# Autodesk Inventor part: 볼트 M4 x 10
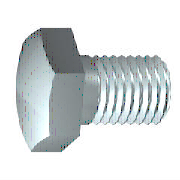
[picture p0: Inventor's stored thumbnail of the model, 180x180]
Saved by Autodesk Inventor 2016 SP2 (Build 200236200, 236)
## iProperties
Created: 2012-02
Part Number: 볼트 M4 x 10
Material: 스테인리스강
Description: 6각 머리 나사
Document SubType Name: Modeling
Standard: ISO 4017
Designer: mduedu
Standard Revision: Third edition 1999-08-15
Standards Organization: ISO
Language: ko-KR
Size Designation: M4 x 10
Categories: <MemberInstance><Categories><Category DisplayName="조임쇠" InternalName="e4da775c-781d-43d5-af7c-5136215cf5a6" Mnemonic="FSTN"><Category DisplayName="볼트" InternalN
Density: 8.08 g/cm^3
Appearance: 반광택
IsCustomPart: 0
Author: mduedu
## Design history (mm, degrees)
sketch "스케치1"
  geometry: L1 (0, 3.015)-(0, 2); L2 (2.1, 2)-(10, 2); L3 (10, 2)-(10, 0); L4 (10, 0)-(-0.4, 0); L5 (-2.48, 0)-(12.08, 0) reference; L6 (-0.4, 0)-(-0.4, 3.015); L7 (-0.4, 3.015)-(0, 3.015); L8 (2.1, 2)-(1.67, 2); L9 (1.67, 2)-(0, 2); L10 (0, -0.603)-(0, 3.618) reference
  constraints: 16 end point, 2 collinear, 2 perpendicular, 1 parallel
  dimensions: "d0" = 10 distance between parallel lines of L3 L1 (= NLG); "d1" = 7.9 distance from line of L2.start L3 (= GEL); "d2" = 4 diameter of L2 L4 (= GD); "d9" = 0.4001 distance between parallel lines of L6 L1 (computed from SD); "d10" = 6.03 diameter of L7 L4 (= SD2); "d13" = 0.42952 distance of L2.start L8.end (computed from GAL); "d14" = 4 diameter of L9 L4 (= BDM)
revolve "본체" sketch "스케치1" stored, may be unused: angle "d12" = 90 deg
sketch "스케치2"
  geometry: L1 (0, 4.041)-(3.5, 2.021); L2 (3.5, 2.021)-(3.5, -2.021); L3 (3.5, -2.021)-(0, -4.041); L4 (0, -4.041)-(-3.5, -2.021); L5 (-3.5, -2.021)-(-3.5, 2.021); L6 (-3.5, 2.021)-(0, 4.041); 2 further points
  constraints: 12 end point, 1 coincident, 1 vertical, 11 other
  dimensions: "d11" = 7 distance between parallel lines of L5 L2 (= SW)
extrude "머리" join sketch "스케치2" distance "d3" = 2.4 (= KOH - SD); taper "d4" = 0 deg
sketch "스케치4"
  geometry: L1 (-2.8, 3.5)-(-2.8, 4.041); L2 (-2.8, 4.041)-(-2.487, 4.041); L3 (-2.487, 4.041)-(-2.8, 3.5); L4 (-3.28, 0)-(0.08, 0) reference; L5 (-0.4, 4.041)-(-2.8, 4.041) reference; L6 (-2.8, 2.021)-(-2.8, 4.041) reference
  constraints: 6 end point, 2 collinear, 1 perpendicular, 1 vertical
  dimensions: "d5" = 30 deg angle of L3 L1 (= ANG1); "d19" = 7 diameter of L1.start L4 (= SW0)
revolve "모따기1" sketch "스케치4" stored, may be unused: angle "d21" = 90 deg
workplane "Work Plane1"
body "Solid1"
feature "스레드" dims "d15" = 7.9 (= GEL), "d16" = 0
chamfer "모따기2" distance "d6" = 0.42941 (= -0.5 x SPD + 0.5 x GD); stored, may be unused: second distance "d7" = 0.42952 (computed from GUL), angle "d55" = 45 deg
other parameters: "NLG" = 10 [user parameter; used in 1 equation term], "GD" = 4 (= NND) [user parameter; used in 2 equation terms], "BDM" = 4 (= NND) [user parameter; used in 1 equation term], "KOH" = 2.8 [user parameter; used in 1 equation term], "GEL" = 7.9 [user parameter; used in 2 equation terms], "SW" = 7 [user parameter; used in 2 equation terms], "SW0" = 7 (= SW) [user parameter; used in 1 equation term], "SPD" = 3.14117 (= NND - 1.2269 x PTC) [user parameter; used in 1 equation term], "SD2" = 6.03 [user parameter; used in 2 equation terms], "SD" = 0.4 [user parameter; used in 2 equation terms], "ANG1" = 30 deg [user parameter; used in 1 equation term], "GAL" = 0.42941 (= 0.61345 x PTC) [user parameter; used in 1 equation term], "GUL" = 0.42941 (= 0.61345 x PTC) [user parameter; used in 1 equation term], "d8" = 0, "RR" = 0.2 [user parameter], "d57" = 0, "d58" = 0, "TPU" = 14.28571 (computed from PTC) [user parameter], "GD1" = 3.14117 (= THREADDIA - 1.2269 x PTC) [user parameter], "THREADDIA" = 4 [user parameter; used in 1 equation term], "SDH" = 6.03 (= SD2) [user parameter], "SDHG" = 2.1 [user parameter], "TOA" = 30 deg [user parameter], "PTC" = 0.7 [user parameter; used in 5 equation terms], "NND" = 4 [user parameter; used in 3 equation terms], "E0" = 8.085 [user parameter]
